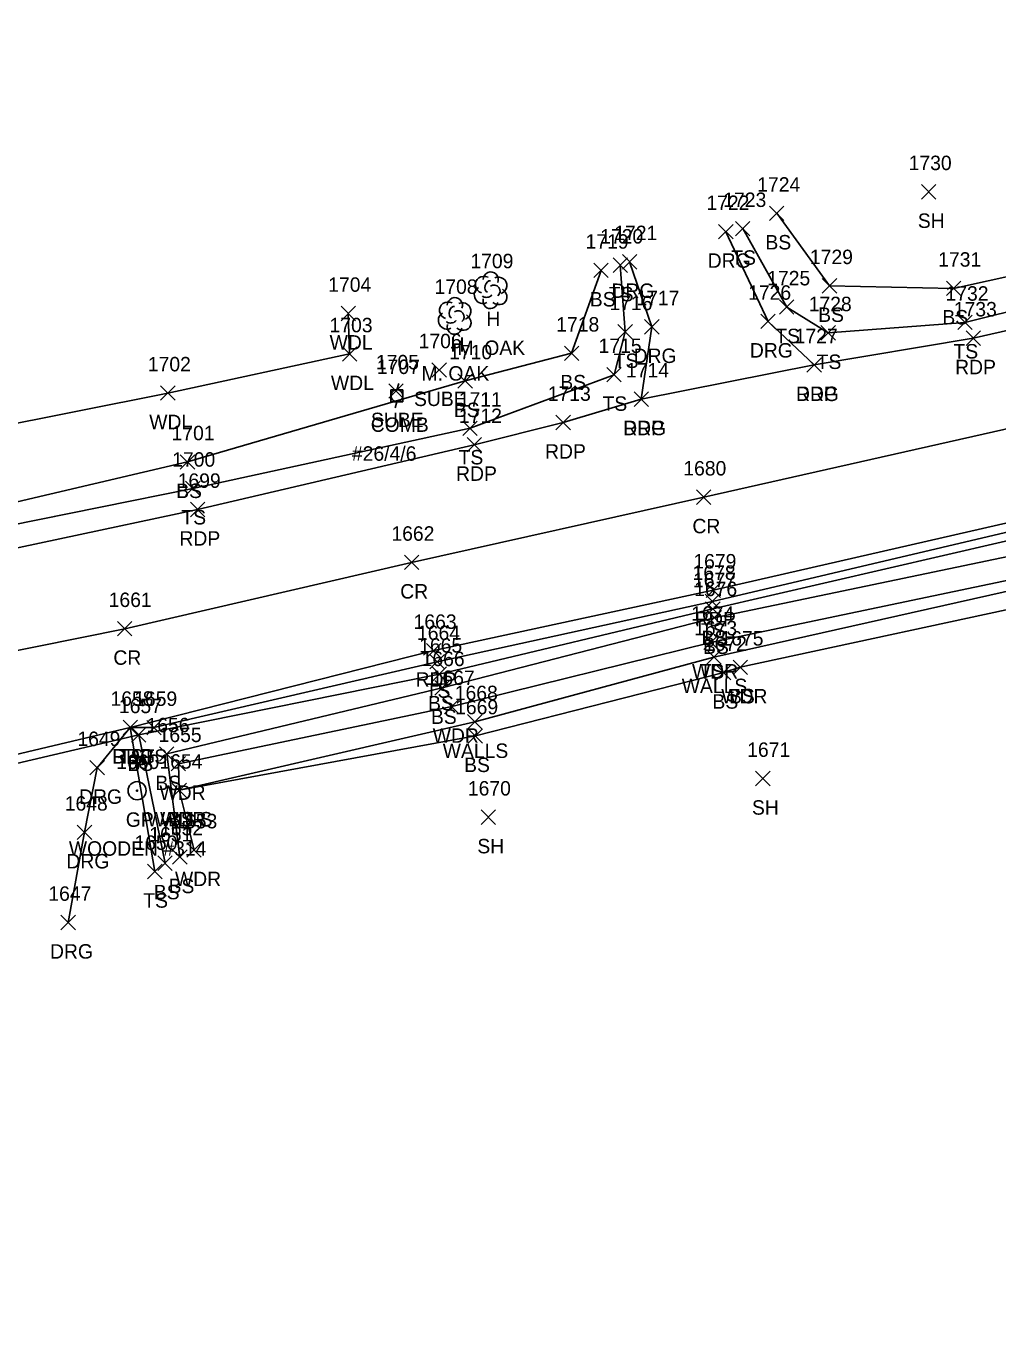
# Model space of a CAD drawing. Extents: x 1611797 to 1633212, y 298978 to 305475.
# Drawn here: x 1613443.8 to 1613578.2, y 301197.3 to 301378 of the extents above; entities that cross this region are included whole.
import ezdxf

# ---------------------------------------------------------------- set-up
doc = ezdxf.new("R2010")
doc.units = 0
for name, color, linetype in [('D_A', 7, 'Continuous'), ('D_I', 7, 'Continuous'), ('D_TIC', 7, 'Continuous'), ('DCP', 7, 'Continuous'), ('L_A', 7, 'Continuous'), ('L_C', 7, 'Continuous'), ('L_I', 7, 'Continuous'), ('L_TIC', 7, 'Continuous'), ('LAWA', 7, 'Continuous'), ('LELB', 7, 'Continuous'), ('LTD', 7, 'Continuous'), ('LWS', 7, 'Continuous'), ('P_A', 7, 'Continuous'), ('P_I', 7, 'Continuous'), ('P_TIC', 7, 'Continuous'), ('PET', 7, 'Continuous'), ('PRC', 7, 'Continuous'), ('R_A', 7, 'Continuous'), ('R_C', 7, 'Continuous'), ('R_I', 7, 'Continuous'), ('R_TIC', 7, 'Continuous'), ('RDG', 7, 'Continuous'), ('RGP', 7, 'Continuous'), ('U_A', 7, 'Continuous'), ('U_C', 7, 'Continuous'), ('U_I', 7, 'Continuous'), ('U_TIC', 7, 'Continuous'), ('UP', 7, 'Continuous')]:
    doc.layers.add(name, color=color, linetype=linetype)

msp = doc.modelspace()

# ---------------------------------------------------------------- linework, layer by layer
at = {"layer": 'D_TIC'}
for points in [[(1613458.37, 301278.97), (1613460.37, 301280.97)], [(1613460.37, 301278.97), (1613458.37, 301280.97)]]:
    msp.add_lwpolyline(points, dxfattribs=at)
at = {"layer": 'DCP'}
msp.add_lwpolyline([(1613429.83, 301273.05), (1613459.37, 301279.97)], dxfattribs=at)
at = {"layer": 'L_TIC'}
for points in [[(1613567.68, 301354.12), (1613569.68, 301356.12)], [(1613569.68, 301354.12), (1613567.68, 301356.12)], [(1613546.64, 301351.14), (1613548.64, 301353.14)], [(1613548.64, 301351.14), (1613546.64, 301353.14)], [(1613541.94, 301349.02), (1613543.94, 301351.02)], [(1613543.94, 301349.02), (1613541.94, 301351.02)], [(1613525, 301343.96), (1613527, 301345.96)], [(1613527, 301343.96), (1613525, 301345.96)], [(1613522.34, 301343.25), (1613524.34, 301345.25)], [(1613524.34, 301343.25), (1613522.34, 301345.25)], [(1613553.94, 301341.11), (1613555.94, 301343.11)], [(1613555.94, 301341.11), (1613553.94, 301343.11)], [(1613571.12, 301340.76), (1613573.12, 301342.76)], [(1613573.12, 301340.76), (1613571.12, 301342.76)], [(1613548.03, 301338.17), (1613550.03, 301340.17)], [(1613550.03, 301338.17), (1613548.03, 301340.17)], [(1613487.36, 301337.28), (1613489.36, 301339.28)], [(1613489.36, 301337.28), (1613487.36, 301339.28)], [(1613525.68, 301334.74), (1613527.68, 301336.74)], [(1613527.68, 301334.74), (1613525.68, 301336.74)], [(1613553.76, 301334.6), (1613555.76, 301336.6)], [(1613555.76, 301334.6), (1613553.76, 301336.6)], [(1613572.69, 301336.05), (1613574.69, 301338.05)], [(1613574.69, 301336.05), (1613572.69, 301338.05)], [(1613487.54, 301331.68), (1613489.54, 301333.68)], [(1613489.54, 301331.68), (1613487.54, 301333.68)], [(1613518.26, 301331.78), (1613520.26, 301333.78)], [(1613520.26, 301331.78), (1613518.26, 301333.78)], [(1613503.53, 301327.94), (1613505.53, 301329.94)], [(1613505.53, 301327.94), (1613503.53, 301329.94)], [(1613524.13, 301328.81), (1613526.13, 301330.81)], [(1613526.13, 301328.81), (1613524.13, 301330.81)], [(1613462.4, 301326.27), (1613464.4, 301328.27)], [(1613464.4, 301326.27), (1613462.4, 301328.27)], [(1613504.21, 301321.39), (1613506.21, 301323.39)], [(1613506.21, 301321.39), (1613504.21, 301323.39)], [(1613465.11, 301316.74), (1613467.11, 301318.74)], [(1613467.11, 301316.74), (1613465.11, 301318.74)], [(1613465.86, 301313.08), (1613467.86, 301315.08)], [(1613467.86, 301313.08), (1613465.86, 301315.08)], [(1613537.75, 301297.42), (1613539.75, 301299.42)], [(1613539.75, 301297.42), (1613537.75, 301299.42)], [(1613537.8, 301296.39), (1613539.8, 301298.39)], [(1613539.8, 301296.39), (1613537.8, 301298.39)], [(1613538.01, 301295.17), (1613540.01, 301297.17)], [(1613540.01, 301295.17), (1613538.01, 301297.17)], [(1613537.55, 301291.76), (1613539.55, 301293.76)], [(1613539.55, 301291.76), (1613537.55, 301293.76)], [(1613537.55, 301291.76), (1613539.55, 301293.76)], [(1613539.55, 301291.76), (1613537.55, 301293.76)], [(1613537.96, 301289.74), (1613539.96, 301291.74)], [(1613539.96, 301289.74), (1613537.96, 301291.74)], [(1613499.66, 301289.09), (1613501.66, 301291.09)], [(1613501.66, 301289.09), (1613499.66, 301291.09)], [(1613539.31, 301287.59), (1613541.31, 301289.59)], [(1613541.31, 301287.59), (1613539.31, 301289.59)], [(1613541.6, 301288.32), (1613543.6, 301290.32)], [(1613543.6, 301288.32), (1613541.6, 301290.32)], [(1613541.6, 301288.32), (1613543.6, 301290.32)], [(1613543.6, 301288.32), (1613541.6, 301290.32)], [(1613499.95, 301287.36), (1613501.95, 301289.36)], [(1613501.95, 301287.36), (1613499.95, 301289.36)], [(1613500.35, 301285.48), (1613502.35, 301287.48)], [(1613502.35, 301285.48), (1613500.35, 301287.48)], [(1613501.68, 301282.87), (1613503.68, 301284.87)], [(1613503.68, 301282.87), (1613501.68, 301284.87)], [(1613504.88, 301280.77), (1613506.88, 301282.77)], [(1613506.88, 301280.77), (1613504.88, 301282.77)], [(1613457.2, 301279.99), (1613459.2, 301281.99)], [(1613459.2, 301279.99), (1613457.2, 301281.99)], [(1613458.37, 301278.97), (1613460.37, 301280.97)], [(1613460.37, 301278.97), (1613458.37, 301280.97)], [(1613460.48, 301279.97), (1613462.48, 301281.97)], [(1613462.48, 301279.97), (1613460.48, 301281.97)], [(1613504.95, 301278.82), (1613506.95, 301280.82)], [(1613506.95, 301278.82), (1613504.95, 301280.82)], [(1613462.24, 301276.32), (1613464.24, 301278.32)], [(1613464.24, 301276.32), (1613462.24, 301278.32)], [(1613463.86, 301274.97), (1613465.86, 301276.97)], [(1613465.86, 301274.97), (1613463.86, 301276.97)], [(1613544.73, 301272.92), (1613546.73, 301274.92)], [(1613546.73, 301272.92), (1613544.73, 301274.92)], [(1613463.97, 301271.29), (1613465.97, 301273.29)], [(1613465.97, 301271.29), (1613463.97, 301273.29)], [(1613463.97, 301271.29), (1613465.97, 301273.29)], [(1613465.97, 301271.29), (1613463.97, 301273.29)], [(1613463.97, 301271.29), (1613465.97, 301273.29)], [(1613465.97, 301271.29), (1613463.97, 301273.29)], [(1613506.74, 301267.57), (1613508.74, 301269.57)], [(1613508.74, 301267.57), (1613506.74, 301269.57)], [(1613466.02, 301263.03), (1613468.02, 301265.03)], [(1613468.02, 301263.03), (1613466.02, 301265.03)], [(1613462.01, 301261.21), (1613464.01, 301263.21)], [(1613464.01, 301261.21), (1613462.01, 301263.21)], [(1613464.06, 301262.06), (1613466.06, 301264.06)], [(1613466.06, 301262.06), (1613464.06, 301264.06)], [(1613460.59, 301260.05), (1613462.59, 301262.05)], [(1613462.59, 301260.05), (1613460.59, 301262.05)]]:
    msp.add_lwpolyline(points, dxfattribs=at)
at = {"layer": 'LAWA'}
for points in [[(1613116.05, 301241.71), (1613152.1, 301256.82), (1613187.94, 301264.96), (1613227.98, 301276.3), (1613260.36, 301288.32), (1613303.07, 301296.61), (1613341.82, 301303.26), (1613387.3, 301310.61), (1613425.64, 301319.75), (1613463.4, 301327.27), (1613488.54, 301332.68), (1613488.36, 301338.28)], [(1613542.6, 301289.32), (1613587.08, 301298.95), (1613620.03, 301306.5), (1613660.53, 301315.68), (1613681.66, 301320), (1613668.45, 301308.3)], [(1613467.02, 301264.03), (1613464.97, 301272.29), (1613464.86, 301275.97), (1613502.68, 301283.87), (1613538.55, 301292.76)]]:
    msp.add_lwpolyline(points, dxfattribs=at)
at = {"layer": 'LELB'}
for points in [[(1613547.64, 301352.14), (1613554.94, 301342.11), (1613572.12, 301341.76), (1613611.33, 301350.41), (1613655.67, 301359.18), (1613687.53, 301366.74), (1613727.39, 301378.05)], [(1613542.94, 301350.02), (1613549.03, 301339.17), (1613554.76, 301335.6), (1613573.69, 301337.05), (1613612.77, 301346.75), (1613656.46, 301356.9), (1613688.22, 301363.65), (1613727.18, 301373.26)], [(1613120.28, 301230.23), (1613159.81, 301240.15), (1613190.29, 301251.12), (1613231.49, 301259.64), (1613266.38, 301267.69), (1613306.33, 301279.13), (1613344.86, 301287.08), (1613390.37, 301296.94), (1613428.5, 301306.3), (1613466.86, 301314.08), (1613505.21, 301322.39), (1613525.13, 301329.81), (1613526.68, 301335.74), (1613526, 301344.96)], [(1613229.97, 301262.54), (1613265.42, 301270.09), (1613305.15, 301282.06), (1613343.72, 301290.47), (1613389.48, 301303.5), (1613427.98, 301308.79), (1613466.11, 301317.74), (1613504.53, 301328.94), (1613519.26, 301332.78), (1613523.34, 301344.25)], [(1613463.01, 301262.21), (1613459.37, 301279.97), (1613500.95, 301288.36), (1613538.8, 301297.39), (1613586.69, 301308.47), (1613620.25, 301315.84), (1613655.44, 301323.72), (1613691.58, 301332.52), (1613692.65, 301329.87)], [(1613465.06, 301263.06), (1613463.24, 301277.32), (1613501.35, 301286.48), (1613539.01, 301296.17), (1613587.16, 301306.24), (1613620.79, 301313.69), (1613656.14, 301321.37), (1613692.65, 301329.87)], [(1613538.55, 301292.76), (1613587.6, 301303.03), (1613620.91, 301310.65), (1613657.17, 301318.76), (1613688.21, 301326.19), (1613694.23, 301328.86)], [(1613461.59, 301261.05), (1613458.2, 301280.99), (1613461.48, 301280.97), (1613500.66, 301290.09), (1613538.75, 301298.42), (1613586.35, 301309.65), (1613620.32, 301317.34), (1613654.96, 301324.72)], [(1613464.97, 301272.29), (1613505.95, 301279.82), (1613540.31, 301288.59), (1613542.6, 301289.32)]]:
    msp.add_lwpolyline(points, dxfattribs=at)
at = {"layer": 'LTD'}
for p, q in [((1613508.04, 301341.54), (1613508.04, 301341.54)), ((1613508.04, 301341.54), (1613508.04, 301341.54)), ((1613503.07, 301337.99), (1613503.07, 301337.99)), ((1613503.07, 301337.99), (1613503.07, 301337.99))]:
    msp.add_line(p, q, dxfattribs=at)
for centre in [(1613508.08, 301342.98), (1613503.11, 301339.43)]:
    msp.add_arc(centre, 1.05, 335.5272, 180.9563, dxfattribs=at)
for centre, major_axis, ratio, start_param, end_param in [((1613507.24, 301342.21), (1.21, -0.51), 0.895232, 1.570796, 4.712389), ((1613506.95, 301340.83), (0.58, -1.04), 0.959034, 3.141593, 6.283185), ((1613507.83, 301342), (-0.208, -0.792), 0.645439, 3.141593, 6.283185), ((1613508.54, 301341.38), (-0.5, 0.667), 0.989748, 3.141593, 6.283185), ((1613509.08, 301342.13), (-1.14, -0.48), 0.949671, 1.570796, 4.712389), ((1613502.28, 301338.66), (1.21, -0.51), 0.895232, 1.570796, 4.712389), ((1613508.04, 301340.04), (0.26, 1.06), 0.942809, 1.570796, 4.712389), ((1613507.58, 301340.79), (-0.625, -0.083), 0.423636, 0, 3.141593), ((1613509.04, 301340.71), (-1.09, 0.79), 0.841452, 1.570796, 4.712389), ((1613501.98, 301337.29), (0.58, -1.04), 0.959034, 3.141593, 6.283185), ((1613502.86, 301338.45), (-0.208, -0.792), 0.645439, 3.141593, 6.283185), ((1613503.57, 301337.83), (-0.5, 0.667), 0.989748, 3.141593, 6.283185), ((1613504.11, 301338.58), (-1.14, -0.48), 0.949671, 1.570796, 4.712389), ((1613503.07, 301336.49), (0.26, 1.06), 0.942809, 1.570796, 4.712389), ((1613502.61, 301337.24), (-0.625, -0.083), 0.423636, 0, 3.141593), ((1613504.07, 301337.16), (-1.09, 0.79), 0.841452, 1.570796, 4.712389)]:
    msp.add_ellipse(centre, major_axis=major_axis, ratio=ratio, start_param=start_param, end_param=end_param, dxfattribs=at)
at = {"layer": 'LWS'}
msp.add_lwpolyline([(1613464.97, 301272.29), (1613505.88, 301281.77), (1613538.96, 301290.74), (1613587.58, 301301.66), (1613621.04, 301309.2), (1613660.53, 301317.03), (1613688.84, 301324.24)], dxfattribs=at)
at = {"layer": 'P_TIC'}
for points in [[(1613573.84, 301333.87), (1613575.84, 301335.87)], [(1613575.84, 301333.87), (1613573.84, 301335.87)], [(1613551.82, 301330.16), (1613553.82, 301332.16)], [(1613553.82, 301330.16), (1613551.82, 301332.16)], [(1613527.91, 301325.43), (1613529.91, 301327.43)], [(1613529.91, 301325.43), (1613527.91, 301327.43)], [(1613517.1, 301322.19), (1613519.1, 301324.19)], [(1613519.1, 301322.19), (1613517.1, 301324.19)], [(1613504.79, 301319.12), (1613506.79, 301321.12)], [(1613506.79, 301319.12), (1613504.79, 301321.12)], [(1613536.55, 301311.86), (1613538.55, 301313.86)], [(1613538.55, 301311.86), (1613536.55, 301313.86)], [(1613466.51, 301310.15), (1613468.51, 301312.15)], [(1613468.51, 301310.15), (1613466.51, 301312.15)], [(1613496.12, 301302.83), (1613498.12, 301304.83)], [(1613498.12, 301302.83), (1613496.12, 301304.83)], [(1613537.86, 301298.99), (1613539.86, 301300.99)], [(1613539.86, 301298.99), (1613537.86, 301300.99)], [(1613456.43, 301293.66), (1613458.43, 301295.66)], [(1613458.43, 301293.66), (1613456.43, 301295.66)], [(1613499.19, 301290.63), (1613501.19, 301292.63)], [(1613501.19, 301290.63), (1613499.19, 301292.63)], [(1613457.2, 301279.99), (1613459.2, 301281.99)], [(1613459.2, 301279.99), (1613457.2, 301281.99)]]:
    msp.add_lwpolyline(points, dxfattribs=at)
at = {"layer": 'PET'}
for points in [[(1613121.41, 301224.79), (1613160.56, 301237.68), (1613191.83, 301246.9), (1613232.03, 301257.4), (1613266.78, 301265.99), (1613307.07, 301275.59), (1613345.71, 301284.52), (1613390.57, 301294.41), (1613429.34, 301303.04), (1613467.51, 301311.15), (1613505.79, 301320.12), (1613518.1, 301323.19), (1613528.91, 301326.43), (1613552.82, 301331.16), (1613574.84, 301334.87), (1613613.75, 301343.67), (1613657.08, 301353.59), (1613689.79, 301361.01), (1613727.87, 301369.49)], [(1613125.52, 301197.34), (1613165.46, 301210.56), (1613197.64, 301220.33), (1613235.96, 301230.65), (1613275.93, 301240.9), (1613310.52, 301248.77), (1613348.15, 301257.49), (1613383.51, 301265), (1613415.7, 301272.42), (1613432.15, 301275.92), (1613434.22, 301275.29), (1613458.2, 301280.99), (1613500.19, 301291.63), (1613538.86, 301299.99), (1613586, 301310.77), (1613620.22, 301318.42), (1613654.85, 301326.13), (1613688.18, 301333.49), (1613701.72, 301336.19), (1613728.29, 301342.74)]]:
    msp.add_lwpolyline(points, dxfattribs=at)
at = {"layer": 'PRC'}
msp.add_lwpolyline([(1613120.36, 301208.99), (1613162.25, 301223.48), (1613195.66, 301233.48), (1613234.87, 301243.9), (1613270.14, 301252.64), (1613310.48, 301262.07), (1613348.55, 301270.95), (1613393.4, 301280.86), (1613432.68, 301289.65), (1613457.43, 301294.66), (1613497.12, 301303.83), (1613537.55, 301312.86), (1613582.34, 301322.95), (1613618.43, 301331.26), (1613657.96, 301340.09), (1613693.64, 301348.14), (1613730.35, 301356.23)], dxfattribs=at)
at = {"layer": 'R_TIC'}
for points in [[(1613539.6, 301348.6), (1613541.6, 301350.6)], [(1613541.6, 301348.6), (1613539.6, 301350.6)], [(1613526.29, 301344.43), (1613528.29, 301346.43)], [(1613528.29, 301344.43), (1613526.29, 301346.43)], [(1613545.44, 301336.18), (1613547.44, 301338.18)], [(1613547.44, 301336.18), (1613545.44, 301338.18)], [(1613529.36, 301335.43), (1613531.36, 301337.43)], [(1613531.36, 301335.43), (1613529.36, 301337.43)], [(1613551.82, 301330.16), (1613553.82, 301332.16)], [(1613553.82, 301330.16), (1613551.82, 301332.16)], [(1613527.91, 301325.43), (1613529.91, 301327.43)], [(1613529.91, 301325.43), (1613527.91, 301327.43)], [(1613457.2, 301279.99), (1613459.2, 301281.99)], [(1613459.2, 301279.99), (1613457.2, 301281.99)], [(1613452.62, 301274.42), (1613454.62, 301276.42)], [(1613454.62, 301274.42), (1613452.62, 301276.42)], [(1613450.87, 301265.48), (1613452.87, 301267.48)], [(1613452.87, 301265.48), (1613450.87, 301267.48)], [(1613448.6, 301253), (1613450.6, 301255)], [(1613450.6, 301253), (1613448.6, 301255)]]:
    msp.add_lwpolyline(points, dxfattribs=at)
at = {"layer": 'RDG'}
for points in [[(1613540.6, 301349.6), (1613546.44, 301337.18), (1613552.82, 301331.16)], [(1613528.91, 301326.43), (1613530.36, 301336.43), (1613527.29, 301345.43)], [(1613449.6, 301254), (1613451.87, 301266.48), (1613453.62, 301275.42), (1613458.2, 301280.99)]]:
    msp.add_lwpolyline(points, dxfattribs=at)
at = {"layer": 'RGP'}
msp.add_line((1613459.14, 301272.24), (1613459.14, 301272.24), dxfattribs=at)
for radius in [1.25, 0.0833]:
    msp.add_circle((1613459.14, 301272.24), radius, dxfattribs=at)
at = {"layer": 'U_TIC'}
for points in [[(1613499.93, 301329.47), (1613501.93, 301331.47)], [(1613501.93, 301329.47), (1613499.93, 301331.47)], [(1613493.96, 301326.55), (1613495.96, 301328.55)], [(1613495.96, 301326.55), (1613493.96, 301328.55)]]:
    msp.add_lwpolyline(points, dxfattribs=at)
at = {"layer": 'UP'}
for p, q in [((1613494.25, 301326.07), (1613494.25, 301327.73)), ((1613494.25, 301327.73), (1613495.92, 301327.73)), ((1613495.34, 301328.57), (1613495.09, 301327.73)), ((1613495.92, 301327.73), (1613495.92, 301326.07)), ((1613495.92, 301326.07), (1613494.25, 301326.07)), ((1613494.84, 301325.23), (1613495.09, 301326.07)), ((1613495.09, 301326.9), (1613495.09, 301326.9))]:
    msp.add_line(p, q, dxfattribs=at)
msp.add_circle((1613495.09, 301326.9), 0.833, dxfattribs=at)

# ---------------------------------------------------------------- texts
at = {"layer": 'D_A'}
msp.add_text('P', height=2, dxfattribs=at).set_placement((1613458.75, 301274.97))
at = {"layer": 'D_I'}
msp.add_text('1657', height=2, dxfattribs=at).set_placement((1613456.63, 301282.97))
at = {"layer": 'L_A'}
for s, p in [('SH', (1613567.17, 301350.12)), ('BS', (1613546.08, 301347.14)), ('TS', (1613541.35, 301345.02)), ('TS', (1613524.41, 301339.96)), ('BS', (1613521.78, 301339.25)), ('H', (1613507.47, 301336.54)), ('BS', (1613553.38, 301337.11)), ('BS', (1613570.56, 301336.76)), ('WDL', (1613485.78, 301333.28)), ('H', (1613502.5, 301332.99)), ('TS', (1613547.44, 301334.17)), ('TS', (1613525.09, 301330.74)), ('TS', (1613572.1, 301332.05)), ('TS', (1613553.17, 301330.6)), ('WDL', (1613485.96, 301327.68)), ('BS', (1613517.7, 301327.78)), ('BS', (1613502.97, 301323.94)), ('TS', (1613523.54, 301324.81)), ('WDL', (1613460.82, 301322.27)), ('TS', (1613503.62, 301317.39)), ('BS', (1613464.55, 301312.74)), ('TS', (1613465.27, 301309.08)), ('TS', (1613537.16, 301293.42)), ('BS', (1613537.24, 301292.39)), ('BS', (1613537.45, 301291.17)), ('WDR', (1613535.92, 301287.76)), ('TS', (1613536.96, 301287.76)), ('WALLS', (1613534.5, 301285.74)), ('TS', (1613499.07, 301285.09)), ('WDR', (1613539.97, 301284.32)), ('BS', (1613541.04, 301284.32)), ('BS', (1613499.4, 301283.36)), ('BS', (1613538.75, 301283.59)), ('BS', (1613499.8, 301281.48)), ('WDR', (1613500.04, 301278.87)), ('WALLS', (1613501.43, 301276.77)), ('TS', (1613456.61, 301275.99)), ('BS', (1613457.81, 301274.97)), ('TS', (1613459.89, 301275.97)), ('BS', (1613504.39, 301274.82)), ('BS', (1613461.68, 301272.32)), ('WDR', (1613462.23, 301270.97)), ('SH', (1613544.22, 301268.92)), ('WALLS', (1613460.51, 301267.29)), ('WDR', (1613462.33, 301267.29)), ('BS', (1613463.41, 301267.29)), ('SH', (1613506.22, 301263.57)), ('WDR', (1613464.38, 301259.03)), ('BS', (1613461.45, 301257.21)), ('BS', (1613463.5, 301258.06)), ('TS', (1613460, 301256.05))]:
    msp.add_text(s, height=2, dxfattribs=at).set_placement(p)
at = {"layer": 'L_C'}
for p in [(1613503.47, 301332.54), (1613498.5, 301328.99)]:
    msp.add_text('M. OAK', height=2, dxfattribs=at).set_placement(p)
at = {"layer": 'L_I'}
for s, p in [('1730', (1613565.9, 301358.12)), ('1724', (1613544.95, 301355.14)), ('1723', (1613540.25, 301353.02)), ('1719', (1613521.2, 301347.25)), ('1720', (1613523.22, 301347.96)), ('1709', (1613505.26, 301344.54)), ('1729', (1613552.24, 301345.11)), ('1731', (1613569.99, 301344.76)), ('1725', (1613546.33, 301342.17)), ('1704', (1613485.59, 301341.28)), ('1708', (1613500.3, 301340.99)), ('1732', (1613571, 301340.05)), ('1716', (1613524.5, 301338.74)), ('1728', (1613552.07, 301338.6)), ('1703', (1613485.77, 301335.68)), ('1718', (1613517.14, 301335.78)), ('1715', (1613523, 301332.81)), ('1710', (1613502.32, 301331.94)), ('1702', (1613460.63, 301330.27)), ('1711', (1613503.65, 301325.39)), ('1701', (1613463.91, 301320.74)), ('1700', (1613464, 301317.08)), ('1678', (1613536.01, 301301.42)), ('1677', (1613536.06, 301300.39)), ('1676', (1613536.22, 301299.17)), ('1674', (1613535.81, 301295.76)), ('1674', (1613535.81, 301295.76)), ('1664', (1613497.87, 301293.09)), ('1673', (1613536.22, 301293.74)), ('1665', (1613498.17, 301291.36)), ('1672', (1613537.57, 301291.59)), ('1675', (1613539.86, 301292.32)), ('1675', (1613539.86, 301292.32)), ('1666', (1613498.51, 301289.48)), ('1667', (1613499.9, 301286.87)), ('1658', (1613455.46, 301283.99)), ('1659', (1613458.74, 301283.97)), ('1668', (1613503.1, 301284.77)), ('1657', (1613456.63, 301282.97)), ('1669', (1613503.15, 301282.82)), ('1656', (1613460.44, 301280.32)), ('1655', (1613462.12, 301278.97)), ('1671', (1613543.56, 301276.92)), ('1654', (1613462.23, 301275.29)), ('1654', (1613462.23, 301275.29)), ('1654', (1613462.23, 301275.29)), ('1670', (1613504.91, 301271.57)), ('1652', (1613462.32, 301266.06)), ('1653', (1613464.28, 301267.03)), ('1650', (1613458.77, 301264.05)), ('1651', (1613460.83, 301265.21))]:
    msp.add_text(s, height=2, dxfattribs=at).set_placement(p)
at = {"layer": 'P_A'}
for s, p in [('RDP', (1613572.33, 301329.87)), ('RDP', (1613550.31, 301326.16)), ('RDP', (1613526.4, 301321.43)), ('RDP', (1613515.59, 301318.19)), ('RDP', (1613503.28, 301315.12)), ('CR', (1613535.98, 301307.86)), ('RDP', (1613465, 301306.15)), ('CR', (1613495.55, 301298.83)), ('RDP', (1613536.35, 301294.99)), ('CR', (1613455.86, 301289.66)), ('RDP', (1613497.68, 301286.63)), ('RDP', (1613455.69, 301275.99))]:
    msp.add_text(s, height=2, dxfattribs=at).set_placement(p)
at = {"layer": 'P_I'}
for s, p in [('1733', (1613572.15, 301337.87)), ('1727', (1613550.13, 301334.16)), ('1714', (1613526.79, 301329.43)), ('1713', (1613515.97, 301326.19)), ('1712', (1613503.67, 301323.12)), ('1680', (1613534.72, 301315.86)), ('1699', (1613464.76, 301314.15)), ('1662', (1613494.33, 301306.83)), ('1679', (1613536.11, 301302.99)), ('1661', (1613455.21, 301297.66)), ('1663', (1613497.4, 301294.63)), ('1658', (1613455.46, 301283.99))]:
    msp.add_text(s, height=2, dxfattribs=at).set_placement(p)
at = {"layer": 'R_A'}
for s, p in [('DRG', (1613538.09, 301344.6)), ('DRG', (1613524.78, 301340.43)), ('DRG', (1613527.84, 301331.43)), ('DRG', (1613543.93, 301332.18)), ('DRG', (1613550.31, 301326.16)), ('DRG', (1613526.4, 301321.43)), ('DRG', (1613455.69, 301275.99)), ('DRG', (1613451.11, 301270.42)), ('GP', (1613457.58, 301267.24)), ('DRG', (1613449.36, 301261.48)), ('DRG', (1613447.09, 301249))]:
    msp.add_text(s, height=2, dxfattribs=at).set_placement(p)
at = {"layer": 'R_C'}
msp.add_text('WOODEN #314', height=2, dxfattribs=at).set_placement((1613449.7, 301263.24))
at = {"layer": 'R_I'}
for s, p in [('1722', (1613537.91, 301352.6)), ('1721', (1613525.17, 301348.43)), ('1726', (1613543.69, 301340.18)), ('1717', (1613528.23, 301339.43)), ('1727', (1613550.13, 301334.16)), ('1714', (1613526.79, 301329.43)), ('1658', (1613455.46, 301283.99)), ('1649', (1613450.88, 301278.42)), ('1660', (1613456.27, 301275.24)), ('1648', (1613449.13, 301269.48)), ('1647', (1613446.86, 301257))]:
    msp.add_text(s, height=2, dxfattribs=at).set_placement(p)
at = {"layer": 'U_A'}
for s, p in [('SUBE', (1613497.46, 301325.47)), ('COMB', (1613491.47, 301321.9)), ('SUBE', (1613491.5, 301322.55))]:
    msp.add_text(s, height=2, dxfattribs=at).set_placement(p)
at = {"layer": 'U_C'}
msp.add_text('#26/4/6', height=2, dxfattribs=at).set_placement((1613488.87, 301317.9))
at = {"layer": 'U_I'}
for s, p in [('1706', (1613498.1, 301333.47)), ('1705', (1613492.19, 301330.55)), ('1707', (1613492.32, 301329.9))]:
    msp.add_text(s, height=2, dxfattribs=at).set_placement(p)

doc.saveas('drawing.dxf')
